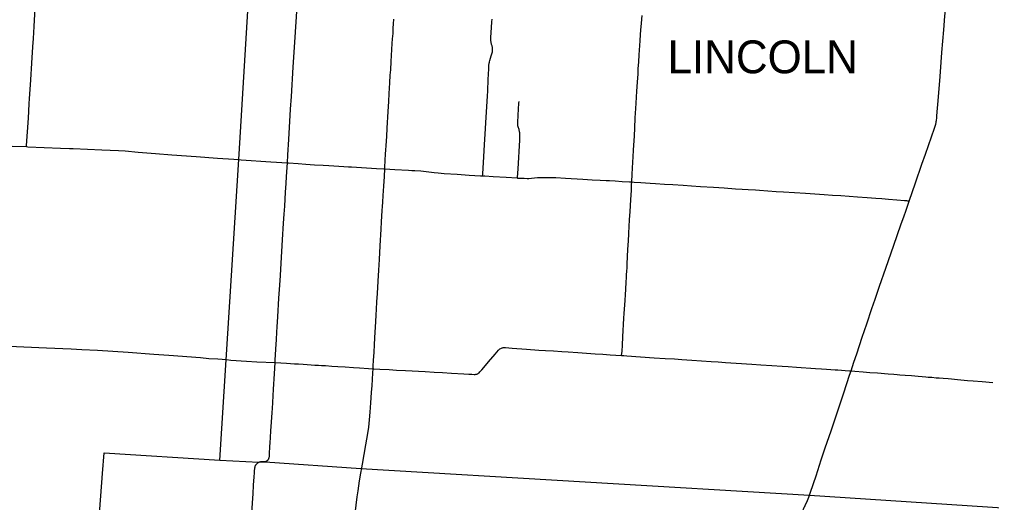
# Model space of a CAD drawing. Extents: x 9078 to 9739, y 4248 to 4966.
# Drawn here: x 9241.2 to 9374.4, y 4419.9 to 4486.1 of the extents above; entities that cross this region are included whole.
import ezdxf

# ---------------------------------------------------------------- set-up
doc = ezdxf.new("R2010")
doc.units = 0
for name, color, linetype in [('GM_X_County_Road', 7, 'Continuous'), ('GM_X_Township', 7, 'Continuous'), ('GM_X_Township_Road', 7, 'Continuous'), ('GM_X_Township_Text', 7, 'Continuous')]:
    doc.layers.add(name, color=color, linetype=linetype)

msp = doc.modelspace()

# ---------------------------------------------------------------- linework, layer by layer
at = {"layer": 'GM_X_County_Road'}
for points in [[(9242.2, 4468.66), (9242.21, 4468.82), (9242.45, 4472.58), (9242.58, 4474.55), (9242.62, 4475.28), (9242.65, 4475.86), (9242.78, 4477.82), (9242.93, 4480.11), (9243.07, 4482.33), (9243.14, 4483.47), (9243.23, 4485.11), (9243.32, 4486.83), (9243.54, 4490.35), (9243.77, 4494.37), (9243.87, 4496.25), (9243.89, 4496.44), (9243.91, 4496.66), (9243.92, 4496.85), (9243.94, 4496.98), (9243.99, 4497.29), (9244.01, 4497.44)], [(9277.94, 4466.43), (9278, 4467.52), (9278.13, 4469.64), (9278.39, 4473.82), (9278.5, 4475.53), (9278.73, 4479.55), (9278.95, 4482.98), (9279.29, 4487.89), (9279.47, 4490.1), (9279.78, 4493.94), (9279.88, 4495.15)], [(9363.15, 4461.2), (9364, 4463.69), (9364.89, 4466.25), (9365.38, 4467.64), (9366.62, 4471.21), (9366.79, 4471.75), (9366.84, 4471.96), (9366.86, 4472.05), (9366.87, 4472.13), (9366.89, 4472.26), (9366.9, 4472.35), (9366.92, 4472.5), (9366.95, 4472.89), (9367.15, 4475.5), (9367.38, 4478.28), (9367.54, 4480.24), (9367.64, 4481.55), (9367.77, 4483.1), (9367.9, 4484.66), (9368.04, 4486.54), (9368.15, 4487.77), (9368.18, 4488.12)], [(9325.13, 4463.82), (9325.19, 4464.9), (9325.29, 4466.54), (9325.33, 4467.28), (9325.39, 4468.18), (9325.5, 4470.14), (9325.55, 4471.21), (9325.62, 4472.6), (9325.69, 4473.91), (9325.73, 4474.64), (9325.85, 4476.28), (9325.92, 4477.51), (9325.99, 4478.65), (9326.03, 4479.31), (9326.1, 4480.29), (9326.16, 4481.27), (9326.28, 4483.15), (9326.35, 4484.05), (9326.39, 4484.62), (9326.47, 4485.6), (9326.55, 4486.66)], [(9291.29, 4465.61), (9291.3, 4465.87), (9291.41, 4467.67), (9291.44, 4468.16), (9291.48, 4468.82), (9291.55, 4470.05), (9291.62, 4471.19), (9291.75, 4473.48), (9291.84, 4474.87), (9291.91, 4475.94), (9291.99, 4477.41), (9292.05, 4478.47), (9292.1, 4479.21), (9292.17, 4480.34), (9292.22, 4481.16), (9292.27, 4481.98), (9292.32, 4482.79), (9292.37, 4483.45), (9292.42, 4484.18), (9292.46, 4484.92), (9292.5, 4485.49), (9292.54, 4486.14)], [(9235.39, 4468.93), (9237.85, 4468.84), (9240.23, 4468.74), (9242.2, 4468.66)], [(9242.2, 4468.66), (9242.36, 4468.65), (9246.87, 4468.46), (9248.1, 4468.41), (9248.59, 4468.39), (9252.52, 4468.23), (9254.82, 4468.14), (9255.72, 4468.09), (9257.51, 4467.91), (9259.88, 4467.72), (9262.09, 4467.55), (9265.44, 4467.3), (9268.39, 4467.08), (9270.6, 4466.93), (9271.17, 4466.89)], [(9271.17, 4466.89), (9271.62, 4466.86)], [(9271.62, 4466.86), (9275.67, 4466.58), (9277.94, 4466.43)], [(9276.26, 4439.06), (9276.27, 4439.37), (9276.37, 4440.92), (9276.44, 4442.23), (9276.5, 4443.21), (9276.55, 4443.96), (9276.63, 4445.34), (9276.79, 4447.88), (9276.9, 4449.68), (9276.98, 4450.99), (9277.08, 4452.71), (9277.28, 4455.9), (9277.43, 4458.19), (9277.51, 4459.41), (9277.58, 4460.48), (9277.7, 4462.44), (9277.78, 4463.59), (9277.83, 4464.57), (9277.94, 4466.43)], [(9277.94, 4466.43), (9278.11, 4466.42), (9279.43, 4466.34), (9280.49, 4466.27), (9281.64, 4466.19), (9282.87, 4466.11), (9283.61, 4466.07), (9285, 4465.98), (9285.66, 4465.94), (9286.32, 4465.9), (9286.73, 4465.88), (9288.12, 4465.79), (9290.17, 4465.67), (9291.16, 4465.62), (9291.29, 4465.61)], [(9289.7, 4438.22), (9289.71, 4438.46), (9289.72, 4438.62), (9289.76, 4439.36), (9289.83, 4440.5), (9289.88, 4441.49), (9289.94, 4442.47), (9290.06, 4444.68), (9290.11, 4445.58), (9290.16, 4446.4), (9290.22, 4447.38), (9290.28, 4448.52), (9290.39, 4450.24), (9290.48, 4451.72), (9290.57, 4453.19), (9290.67, 4455.07), (9290.81, 4457.36), (9290.86, 4458.34), (9290.95, 4459.9), (9290.99, 4460.47), (9291.02, 4461.05), (9291.07, 4461.95), (9291.15, 4463.25), (9291.23, 4464.56), (9291.29, 4465.61)], [(9355.19, 4437.92), (9355.58, 4439.1), (9355.97, 4440.27), (9356.72, 4442.53), (9357.34, 4444.39), (9358.05, 4446.49), (9358.48, 4447.73), (9359.1, 4449.52), (9359.96, 4451.99), (9361.05, 4455.17), (9362.02, 4457.96), (9362.44, 4459.17), (9362.67, 4459.82), (9363.15, 4461.2)], [(9233.57, 4441.6), (9234.04, 4441.58), (9234.85, 4441.54), (9236.01, 4441.49), (9237.8, 4441.4), (9241.82, 4441.23), (9244.93, 4441.1), (9248.3, 4440.94), (9249.77, 4440.86), (9251.91, 4440.77), (9254.03, 4440.63), (9256.15, 4440.48), (9259.66, 4440.21), (9261.72, 4440.07), (9266.05, 4439.75), (9267.18, 4439.64), (9268.43, 4439.56), (9269.59, 4439.46)], [(9269.59, 4439.46), (9270.2, 4439.41), (9272.34, 4439.25), (9273.75, 4439.18), (9276.26, 4439.06)], [(9349.42, 4420.62), (9349.65, 4421.29), (9350.39, 4423.55), (9351.1, 4425.73), (9351.65, 4427.36), (9352.44, 4429.69), (9352.91, 4431.09), (9354.18, 4434.9), (9354.99, 4437.31), (9355.19, 4437.92)], [(9345.27, 4407.93), (9345.64, 4409.07), (9346.49, 4411.64), (9347.05, 4413.35), (9347.58, 4414.99), (9347.88, 4416.01), (9348.36, 4417.84), (9348.54, 4418.51), (9348.58, 4418.66), (9348.6, 4418.73), (9348.64, 4418.85), (9348.67, 4418.95), (9348.72, 4419.1), (9348.78, 4419.24), (9348.83, 4419.35), (9348.89, 4419.48), (9349.22, 4420.14), (9349.31, 4420.36), (9349.41, 4420.59), (9349.42, 4420.62)]]:
    msp.add_lwpolyline(points, dxfattribs=at)
at = {"layer": 'GM_X_Township'}
for points in [[(9268.7, 4425.69), (9269.56, 4439.45), (9271.28, 4466.88), (9273.01, 4495.59), (9279.84, 4495.18), (9281.14, 4512.56), (9281.77, 4520.95), (9292.78, 4520.16), (9315.04, 4518.59), (9316.33, 4535.68), (9316.53, 4538.57), (9316.88, 4542.9), (9317.03, 4544.83), (9317.72, 4551.99), (9321.23, 4552.3), (9324.03, 4552.6), (9334.67, 4553.48), (9360.11, 4556.51), (9359.51, 4548.55), (9366.32, 4547.91), (9372.85, 4547.27), (9397.66, 4545.2), (9410.41, 4544.24)], [(9250.73, 4399.27), (9251.82, 4413.47), (9252.62, 4423.86), (9252.83, 4426.7), (9268.7, 4425.69), (9274.03, 4425.41), (9274.32, 4425.46), (9274.89, 4425.45), (9288.03, 4424.54), (9349.47, 4420.87), (9376.69, 4419.12)]]:
    msp.add_lwpolyline(points, dxfattribs=at)
at = {"layer": 'GM_X_Township_Road'}
for points in [[(9304.69, 4464.66), (9304.71, 4464.83), (9304.71, 4464.92), (9304.81, 4466.47), (9304.96, 4468.93), (9305.1, 4471.14), (9305.19, 4472.7), (9305.37, 4475.57), (9305.4, 4476.31), (9305.48, 4477.87), (9305.54, 4479.34), (9305.56, 4479.74), (9305.57, 4479.82), (9305.57, 4479.91), (9305.58, 4480.02), (9305.61, 4480.16), (9305.62, 4480.22), (9305.64, 4480.3), (9305.69, 4480.48), (9305.89, 4481.1), (9306.03, 4481.66), (9306.05, 4481.8), (9306.07, 4481.9), (9306.07, 4482.02), (9306.06, 4482.15), (9306.05, 4482.23), (9306.04, 4482.31), (9306.02, 4482.38), (9306, 4482.47), (9305.97, 4482.56), (9305.93, 4482.67), (9305.91, 4482.76), (9305.88, 4482.87), (9305.87, 4482.97), (9305.86, 4483.04), (9305.84, 4483.11), (9305.84, 4483.21), (9305.83, 4483.34), (9305.83, 4483.43), (9305.83, 4483.5), (9305.84, 4483.66), (9305.87, 4484.26), (9305.96, 4485.75), (9305.99, 4486.12)], [(9309.49, 4464.36), (9309.49, 4464.42), (9309.56, 4465.6), (9309.78, 4469.54), (9309.81, 4470.12), (9309.81, 4470.45), (9309.8, 4470.56), (9309.77, 4470.69), (9309.69, 4471.01), (9309.57, 4471.4), (9309.54, 4471.53), (9309.53, 4471.64), (9309.52, 4471.78), (9309.52, 4471.97), (9309.58, 4472.96), (9309.68, 4474.6), (9309.7, 4474.85)], [(9291.29, 4465.61), (9292.65, 4465.53), (9294.53, 4465.42), (9295.02, 4465.39), (9295.43, 4465.38), (9296.25, 4465.33), (9296.58, 4465.3), (9297.31, 4465.21), (9298.04, 4465.12), (9298.61, 4465.06), (9299.43, 4465), (9301.23, 4464.88), (9302.87, 4464.77), (9304.42, 4464.67), (9304.69, 4464.66)], [(9304.69, 4464.66), (9304.99, 4464.64), (9306.14, 4464.58), (9307.94, 4464.46), (9309.41, 4464.37), (9309.49, 4464.36)], [(9309.49, 4464.36), (9310.4, 4464.32), (9310.81, 4464.31), (9311.05, 4464.31), (9311.38, 4464.33), (9312.2, 4464.41), (9312.69, 4464.44), (9313.18, 4464.45), (9313.67, 4464.45), (9314.74, 4464.41), (9316.05, 4464.34), (9318.42, 4464.2), (9319.73, 4464.13), (9320.79, 4464.07), (9321.61, 4464.03), (9322.1, 4464), (9322.84, 4463.96), (9323.82, 4463.9), (9324.81, 4463.85), (9325.13, 4463.82)], [(9323.75, 4440.03), (9323.8, 4440.64), (9323.85, 4441.46), (9323.92, 4442.6), (9324.07, 4445.14), (9324.11, 4445.79), (9324.23, 4447.59), (9324.27, 4448.41), (9324.3, 4449.06), (9324.33, 4449.47), (9324.35, 4449.72), (9324.37, 4449.96), (9324.39, 4450.28), (9324.4, 4450.53), (9324.41, 4450.69), (9324.42, 4450.85), (9324.43, 4451.09), (9324.43, 4451.17), (9324.45, 4451.49), (9324.49, 4452.15), (9324.52, 4452.88), (9324.55, 4453.29), (9324.57, 4453.7), (9324.66, 4455.25), (9324.68, 4455.66), (9324.75, 4456.81), (9324.84, 4458.61), (9324.91, 4459.75), (9325, 4461.39), (9325.08, 4462.7), (9325.12, 4463.6), (9325.13, 4463.68), (9325.13, 4463.82)], [(9325.13, 4463.82), (9325.46, 4463.8), (9326.36, 4463.74), (9327.67, 4463.66), (9328.41, 4463.62), (9329.63, 4463.53), (9330.78, 4463.46), (9332.17, 4463.36), (9333.31, 4463.29), (9334.54, 4463.21), (9336.34, 4463.1), (9337.81, 4463), (9339.37, 4462.9), (9340.27, 4462.84), (9341.09, 4462.78), (9342.07, 4462.72), (9342.64, 4462.68), (9344.93, 4462.53), (9345.92, 4462.47), (9348.94, 4462.28), (9351.48, 4462.1), (9352.62, 4462.02), (9353.77, 4461.95), (9356.06, 4461.79), (9357.37, 4461.7), (9358.6, 4461.61), (9359.41, 4461.55), (9360.31, 4461.47), (9361.46, 4461.39), (9362.52, 4461.3), (9362.76, 4461.28), (9362.93, 4461.25), (9363.04, 4461.23), (9363.15, 4461.2)], [(9289.7, 4438.22), (9289.78, 4438.22), (9290.6, 4438.17), (9291.91, 4438.1), (9292.89, 4438.04), (9294.12, 4437.97), (9296.82, 4437.82), (9298.04, 4437.75), (9299.19, 4437.69), (9300.42, 4437.62), (9302.14, 4437.53), (9302.79, 4437.48), (9303.2, 4437.46), (9303.53, 4437.44), (9303.69, 4437.44), (9303.77, 4437.45), (9303.85, 4437.46), (9303.93, 4437.49), (9304.01, 4437.52), (9304.08, 4437.56), (9304.14, 4437.61), (9304.21, 4437.66), (9304.32, 4437.77), (9304.59, 4438.08), (9305.07, 4438.65), (9305.5, 4439.15), (9306.4, 4440.2), (9306.89, 4440.76), (9307, 4440.88), (9307.07, 4440.93), (9307.2, 4441.01), (9307.28, 4441.05), (9307.36, 4441.07), (9307.44, 4441.09), (9307.52, 4441.11), (9307.68, 4441.11), (9307.85, 4441.11), (9308.74, 4441.04), (9310.71, 4440.89), (9312.42, 4440.78), (9313.32, 4440.72), (9314.39, 4440.65), (9315.53, 4440.57), (9316.43, 4440.52), (9317.74, 4440.44), (9320.11, 4440.28), (9321.18, 4440.21), (9322.16, 4440.14), (9323.75, 4440.03)], [(9323.75, 4440.03), (9324.04, 4440.01), (9324.45, 4439.99), (9326.33, 4439.86), (9328.22, 4439.73), (9329.69, 4439.64), (9331, 4439.55), (9331.99, 4439.48), (9333.38, 4439.38), (9336, 4439.22), (9336.98, 4439.15), (9337.96, 4439.08), (9339.44, 4438.98), (9341.57, 4438.84), (9342.8, 4438.76), (9344.35, 4438.65), (9345.74, 4438.56), (9346.56, 4438.51), (9347.71, 4438.44), (9350.33, 4438.25), (9351.15, 4438.21), (9351.81, 4438.16), (9353.03, 4438.08), (9353.36, 4438.05), (9354.4, 4437.98), (9354.99, 4437.93), (9355.19, 4437.92)], [(9275.59, 4428.07), (9275.62, 4428.78), (9275.67, 4429.68), (9275.75, 4430.91), (9275.85, 4432.21), (9275.89, 4432.78), (9275.93, 4433.6), (9276.03, 4435.4), (9276.16, 4437.52), (9276.26, 4439.06)], [(9276.26, 4439.06), (9277.84, 4438.98), (9278.9, 4438.9), (9279.47, 4438.87), (9280.13, 4438.82), (9280.64, 4438.79), (9281.22, 4438.76), (9281.72, 4438.72), (9282.21, 4438.69), (9282.6, 4438.67), (9283.18, 4438.64), (9284.05, 4438.58), (9284.87, 4438.53), (9285.85, 4438.46), (9287, 4438.39), (9287.81, 4438.33), (9289.04, 4438.25), (9289.7, 4438.22)], [(9288.13, 4424.61), (9288.22, 4425.12), (9288.68, 4427.79), (9288.95, 4429.32), (9289.09, 4430.21), (9289.16, 4430.7), (9289.2, 4431.19), (9289.27, 4432.25), (9289.37, 4433.56), (9289.47, 4434.95), (9289.54, 4435.93), (9289.6, 4436.75), (9289.66, 4437.65), (9289.7, 4438.22)], [(9355.19, 4437.92), (9355.71, 4437.88), (9356.86, 4437.79), (9357.76, 4437.72), (9358.82, 4437.63), (9360.29, 4437.51), (9361.03, 4437.46), (9361.52, 4437.43), (9361.85, 4437.4), (9362.58, 4437.34), (9363.48, 4437.27), (9364.38, 4437.2), (9364.95, 4437.15), (9365.44, 4437.11), (9365.77, 4437.08), (9366.26, 4437.04), (9366.83, 4436.99), (9367.24, 4436.95), (9367.81, 4436.9), (9368.47, 4436.86), (9368.96, 4436.82), (9369.77, 4436.75), (9371.16, 4436.62), (9371.9, 4436.56), (9373.13, 4436.46), (9374.6, 4436.35)], [(9275.49, 4426.25), (9275.49, 4426.29), (9275.5, 4426.38), (9275.51, 4426.53), (9275.56, 4427.56), (9275.59, 4428.07)], [(9273.03, 4417.76), (9273.25, 4421.11), (9273.31, 4422.21), (9273.36, 4422.89), (9273.39, 4423.32), (9273.43, 4424.04), (9273.46, 4424.34), (9273.47, 4424.43), (9273.48, 4424.54), (9273.49, 4424.64), (9273.51, 4424.75), (9273.52, 4424.8), (9273.54, 4424.85), (9273.55, 4424.9), (9273.58, 4424.96), (9273.61, 4425), (9273.62, 4425.03), (9273.64, 4425.06), (9273.68, 4425.1), (9273.74, 4425.17), (9273.85, 4425.27), (9273.91, 4425.32), (9273.97, 4425.36), (9274.04, 4425.39), (9274.09, 4425.42), (9274.13, 4425.43), (9274.17, 4425.45), (9274.22, 4425.46), (9274.25, 4425.47), (9274.29, 4425.48), (9274.36, 4425.48), (9274.39, 4425.49), (9274.41, 4425.49), (9274.45, 4425.49), (9274.49, 4425.49), (9274.56, 4425.49)], [(9274.56, 4425.49), (9274.78, 4425.49), (9274.85, 4425.49), (9274.89, 4425.49), (9274.92, 4425.49), (9274.95, 4425.5), (9274.97, 4425.51), (9275, 4425.51), (9275.03, 4425.53), (9275.07, 4425.55), (9275.13, 4425.59), (9275.17, 4425.61), (9275.2, 4425.63), (9275.23, 4425.66), (9275.27, 4425.7), (9275.32, 4425.75), (9275.34, 4425.79), (9275.37, 4425.82), (9275.39, 4425.88), (9275.42, 4425.94), (9275.43, 4425.98), (9275.45, 4426.03), (9275.46, 4426.09), (9275.48, 4426.16), (9275.49, 4426.25)], [(9286.81, 4411.51), (9286.82, 4411.61), (9286.87, 4412.34), (9286.93, 4413.4), (9287, 4414.71), (9287.08, 4416.11), (9287.12, 4416.76), (9287.19, 4417.82), (9287.24, 4418.39), (9287.37, 4419.53), (9287.52, 4420.67), (9287.63, 4421.48), (9287.83, 4422.86), (9288.01, 4423.91), (9288.13, 4424.61)]]:
    msp.add_lwpolyline(points, dxfattribs=at)

# ---------------------------------------------------------------- texts
at = {"layer": 'GM_X_Township_Text'}
msp.add_text('LINCOLN', height=4.5, rotation=0, dxfattribs=at).set_placement((9330.04, 4478.72))

doc.saveas('drawing.dxf')
